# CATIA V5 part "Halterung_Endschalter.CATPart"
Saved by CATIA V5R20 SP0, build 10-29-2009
Part number: Halterung_Endschalter
Bounding box of the stored display mesh (mm): x 0 to 10, y 0 to 40, z 0 to 31.5
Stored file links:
  C:\Users\Andi\Desktop\Plasma\Halterung_Endschalter.CATPart
  C:\Program Files\Dassault Systemes\B20\win_b64\reffiles\standard\MetricThickPitch.txt
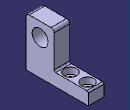
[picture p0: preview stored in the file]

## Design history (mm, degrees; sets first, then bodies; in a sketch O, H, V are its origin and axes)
Body1 (main body)
  Sketch1 on yz-plane, origin (0, 0, 0), H (0, 1, 0), V (0, 0, 1)
    line L1 (0, 0) -> (0, 29.5)
    line L2 (2, 31.5) -> (16, 31.5)
    line L3 (18, 29.5) -> (18, 9)
    line L4 (19, 8) -> (39, 8)
    line L5 (40, 7) -> (40, 0)
    point P1 (40, 0)
    line L6 (40, 0) -> (0, 0)
    construction circle A1 centre (9, 22.5) radius 6
    point P2 (9, 22.5)
    reference intersected line E1 through (0, 0) direction (-1, 0) from xy-plane
    arc A2 centre (2, 29.5) radius 2 from (0, 29.5) to (2, 31.5) cw
    arc A3 centre (16, 29.5) radius 2 from (16, 31.5) to (18, 29.5) cw
    arc A4 centre (19, 9) radius 1 from (18, 9) to (19, 8) ccw
    arc A5 centre (39, 7) radius 1 from (39, 8) to (40, 7) cw
    radius A1 = 6
    distance L1 L3 = 18
    distance P2 L2 = 9
    distance P2 E1 = 22.5
    distance L5 L3 = 22
    distance L4 L6 = 8
    radius A2 = 2
    radius A3 = 2 {= Sketch1.radius(A2)}
    radius A4 = 1
    radius A5 = 1
    vertical: L1 V, L3 V, L5 V
    horizontal: L2 H, L4 H, L6 H
    coincidence: P1 H
    equidistance: L1 L3 P2
    tangency: A2 L1, A2 L2, A3 L2, A3 L3, A4 L3, A4 L4, A5 L4, A5 L5
  Pad1: profile Sketch1, direction (1, 0, 0), length 10
  Sketch2 on face of Pad1 from Sketch1.L4, origin (5.8657, 22.6115, 8), H (1, 0, 0), V (0, 1, 0)
    point P1 (-0.8657, 0.8885)
    reference projected line E1 (-5.8657, 16.3885) -> (-5.8657, -3.6115) from edge [start face of Pad1 | face of Pad1 from Sketch1.L4]
    reference projected line E2 (4.1343, 16.3885) -> (4.1343, -3.6115) from edge [face of Pad1 from Sketch1.L4 | end face of Pad1]
    construction line L1 (-8.5956, 6.3885) -> (4.292, 6.3885)
    reference intersected line E3 through (0, -4.6115) direction (1, 0) from face of Pad1 from Sketch1.L3
    reference intersected line E4 through (0, 17.3885) direction (1, 0) from face of Pad1 from Sketch1.L5
    reference intersected line E5 through (0, -4.6115) direction (1, 0) from face of Pad1 from Sketch1.L3
    equidistance: E1 E2 P1, L1 E5 P1
    horizontal: L1 H
    symmetry: E3 E4 L1
  Hole1: placed by Sketch2, at (5, 23.5, 8) direction (0, 0, -1), diameter 4.3, through (limit type 6), counterbore diameter 8, counterbore depth 4
  RectPattern1: of Hole1, direction 1 instances 2, spacing 11, along face of Pad1 from Sketch1.L4
  Sketch3 on end face of Pad1, origin (10, 8.3969, 23.1598), H (0, 1, 0), V (0, 0, 1)
    point P1 (0.6031, -0.6598)
    reference projected line E1 (-8.3969, 6.3402) -> (-8.3969, -23.1598) from edge [face of Pad1 from Sketch1.L1 | end face of Pad1]
    reference projected line E2 (9.6031, -14.1598) -> (9.6031, 6.3402) from edge [face of Pad1 from Sketch1.L3 | end face of Pad1]
    reference projected line E3 (7.6031, 8.3402) -> (-6.3969, 8.3402) from edge [face of Pad1 from Sketch1.L2 | end face of Pad1]
    distance E3 P1 = 9
    equidistance: E1 E2 P1
  Hole2: placed by Sketch3, at (10, 9, 22.5) direction (-1, 0, 0), diameter 10.106, through (limit type 6), threaded "M12", thread diameter 12, thread depth 10, pitch 1.75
